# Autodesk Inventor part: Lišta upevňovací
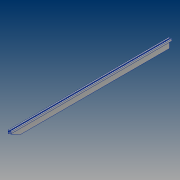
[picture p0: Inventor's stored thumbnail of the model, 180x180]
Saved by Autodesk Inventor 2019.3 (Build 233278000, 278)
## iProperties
Created: 2019-02
Part Number: Lišta upevňovací
Material: Hliník 6061
Document SubType Name: Modeling
Designer: B-hon
Density: 2.7 g/cm^3
Appearance: Hliník – plochý
Author: B-hon
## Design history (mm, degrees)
sketch "Náčrt1"
  geometry: L1 (0, 0)-(5, 0); L2 (30, 78)-(30, 95); L3 (0, 95)-(0, 0); L4 (5, 0)-(5, 78); L5 (5, 78)-(30, 78); L6 (5, 90.5)-(5, 82.5); L7 (25, 82.5)-(25, 90.5); L8 (9.55, 82.5)-(9.55, 85.5); L9 (9.55, 85.5)-(7.55, 85.5); L10 (7.55, 85.5)-(7.55, 82.5); L11 (22.45, 82.5)-(22.45, 85.5); L12 (22.45, 85.5)-(20.45, 85.5); L13 (20.45, 85.5)-(20.45, 82.5); L14 (5, 82.5)-(7.55, 82.5); L15 (9.55, 82.5)-(20.45, 82.5); L16 (22.45, 82.5)-(25, 82.5); L17 (9.55, 95)-(9.55, 90.5); L18 (20.45, 95)-(20.45, 90.5); L19 (30, 95)-(20.45, 95); L20 (9.55, 95)-(0, 95); L21 (25, 90.5)-(20.45, 90.5); L22 (9.55, 90.5)-(5, 90.5)
  constraints: 44 end point, 13 parallel, 6 perpendicular, 3 horizontal, 2 horizontal alignment, 1 point on line, 1 vertical
  dimensions: "d0" = 30 distance of L3.start L2.end; "d3" = 5 distance between parallel lines of L3 L6; "d4" = 5 distance between parallel lines of L2 L7; "d7" = 5 distance between parallel lines of L3 L4; "d8" = 14.9 distance between parallel lines of L11 L10; "d9" = 2 distance between parallel lines of L8 L10; "d10" = 2 distance of L11.end L12.end; "d14" = 2.55 distance between parallel lines of L10 L6; "d15" = 9.55 distance of L17.start L3.start; "d16" = 9.55 distance of L2.end L18.start (= d15); "d17" = 9.5 distance between parallel lines of L12 L19; "d18" = 12.5 distance between parallel lines of L19 L15; "d19" = 17 distance between parallel lines of L5 L19
extrude "Vysunutí1" new body sketch "Náčrt1" distance "d20" = 1600; taper "d21" = 0 deg
chamfer "Zkosení1" distance "d22" = 65; stored, may be unused: second distance "d23" = 2, angle "d24" = 60 deg
node "Těleso1"
other parameters: "d2" = 4.5, "d5" = 17, "d6" = 12.5, "d12" = 12.5, "d13" = 9.5
